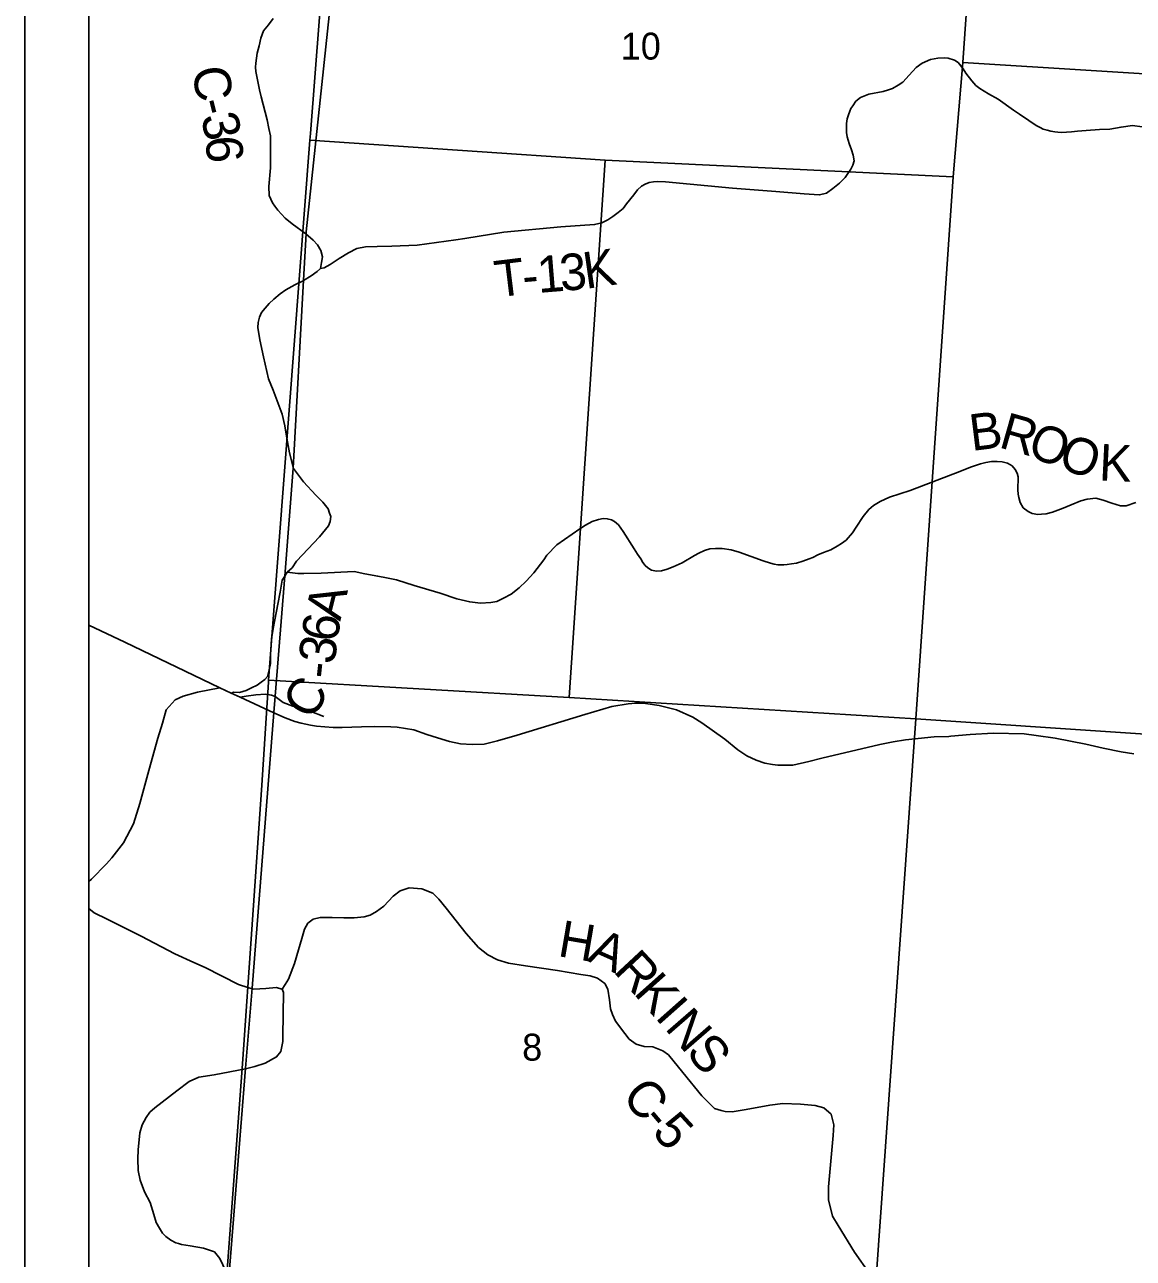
# Model space of a CAD drawing. Extents: x 0 to 34, y 0 to 22.
# Drawn here: x 2 to 3.724, y 16.952 to 18.871 of the extents above; entities that cross this region are included whole.
import ezdxf

# ---------------------------------------------------------------- set-up
doc = ezdxf.new("R2010")
doc.units = 0
for name, color, linetype in [('GM_X_Corporation', 7, 'Continuous'), ('GM_X_County_Road', 7, 'Continuous'), ('GM_X_County_Road_Text', 7, 'Continuous'), ('GM_X_Section_Text', 7, 'Continuous'), ('GM_X_Township_Road', 7, 'Continuous'), ('GM_X_Township_Road_Text', 7, 'Continuous'), ('GM_X_Township_Text', 7, 'Continuous'), ('GM_X_US_Route', 7, 'Continuous'), ('SH_Data', 7, 'Continuous')]:
    doc.layers.add(name, color=color, linetype=linetype)

msp = doc.modelspace()

# ---------------------------------------------------------------- linework, layer by layer
at = {"layer": 'GM_X_Corporation'}
msp.add_lwpolyline([(6.4774, 18.0202), (6.488, 18.1751), (6.5242, 18.7061), (6.5297, 18.7882), (6.5448, 18.981), (6.5455, 18.9878), (6.5461, 19.0017), (6.5463, 19.0089), (6.5469, 19.0218), (6.548, 19.0466), (6.5487, 19.0617), (6.5495, 19.082), (6.5503, 19.0966), (6.5514, 19.1091), (6.5523, 19.1179), (6.5529, 19.1264), (6.5537, 19.1382), (6.5541, 19.1447), (6.5536, 19.1514), (6.5814, 19.5334), (6.6608, 20.6694), (6.6768, 20.9), (2.1, 20.9), (2.1, 14.1)], dxfattribs=at)
for points in [[(3.5308, 19.8461), (4.5379, 19.7849), (4.465, 18.749), (3.459, 18.812), (3.474, 19.0276), (3.5026, 19.4408)], [(2.4767, 19.0934), (3.474, 19.0276), (3.459, 18.812), (3.4438, 18.6342), (2.9025, 18.6602), (2.4436, 18.6909), (2.4444, 18.7015), (2.4582, 18.8825)], [(4.465, 18.749), (4.3947, 17.724), (3.3856, 17.7912), (3.4438, 18.6342), (3.459, 18.812)], [(2.9025, 18.6602), (2.8467, 17.8245), (2.3793, 17.8512), (2.4436, 18.6909)], [(3.4438, 18.6342), (3.3856, 17.7912), (2.8467, 17.8245), (2.9025, 18.6602)], [(2.3791, 17.8483), (2.3793, 17.8512), (2.8467, 17.8245), (3.3856, 17.7912), (3.312, 16.7534), (2.3064, 16.8224), (2.3386, 17.2547), (2.3688, 17.6879)], [(3.3856, 17.7912), (4.3947, 17.724), (4.3249, 16.693), (3.312, 16.7534)]]:
    msp.add_lwpolyline(points, close=True, dxfattribs=at)
at = {"layer": 'GM_X_County_Road'}
for points in [[(2.3864, 18.8801), (2.3791, 18.8703), (2.3714, 18.861), (2.3673, 18.8496), (2.3644, 18.838), (2.3616, 18.8264), (2.3606, 18.8187), (2.3595, 18.8107), (2.359, 18.8045), (2.3593, 18.7981), (2.3603, 18.7926), (2.3624, 18.7823), (2.3652, 18.7692), (2.3678, 18.7586), (2.3771, 18.7225), (2.3799, 18.7094), (2.382, 18.6978), (2.3822, 18.6482), (2.3799, 18.6191), (2.3802, 18.6049), (2.3853, 18.5938), (2.3892, 18.5884)], [(2.3892, 18.5884), (2.3936, 18.5822), (2.4049, 18.5698), (2.416, 18.5608), (2.4374, 18.5456), (2.4488, 18.5358), (2.4552, 18.5286), (2.4604, 18.5196), (2.4632, 18.5098), (2.4617, 18.5007), (2.4602, 18.4915), (2.4549, 18.4869), (2.4456, 18.4803), (2.4338, 18.473), (2.4322, 18.472), (2.4199, 18.4663), (2.406, 18.4585), (2.3971, 18.4521), (2.3874, 18.4441), (2.3804, 18.4373), (2.3738, 18.4301), (2.3683, 18.4229), (2.3651, 18.4159), (2.363, 18.4077), (2.3626, 18.3998), (2.3658, 18.3808), (2.3715, 18.3542), (2.3793, 18.32), (2.3862, 18.3024), (2.4005, 18.2648), (2.4045, 18.247), (2.4079, 18.2277), (2.4119, 18.2051), (2.4179, 18.1808), (2.4335, 18.1597), (2.4528, 18.139), (2.4637, 18.1281), (2.472, 18.118), (2.4742, 18.1111), (2.4759, 18.1057), (2.4748, 18.0983), (2.4723, 18.0913), (2.4587, 18.0744), (2.4227, 18.0363), (2.4159, 18.0263), (2.4084, 18.0193), (2.425, 18.0175), (2.434, 18.0175), (2.4608, 18.0179), (2.5126, 18.0203), (2.5292, 18.0166), (2.5491, 18.0129), (2.5626, 18.0105), (2.578, 18.0072), (2.6058, 17.9988), (2.6461, 17.9865), (2.6721, 17.9779), (2.6922, 17.973), (2.7086, 17.971), (2.7247, 17.972), (2.7342, 17.974), (2.7446, 17.9788), (2.7563, 17.9853), (2.769, 17.9951), (2.78, 18.0052), (2.7915, 18.0181), (2.8072, 18.0383), (2.812, 18.0459), (2.8273, 18.0619), (2.8633, 18.0867), (2.8719, 18.0924), (2.8826, 18.0983), (2.8924, 18.1014), (2.8996, 18.1028), (2.9059, 18.1024), (2.9123, 18.1008), (2.917, 18.0981), (2.9235, 18.0928), (2.9309, 18.0828), (2.9479, 18.0557), (2.953, 18.0471), (2.9579, 18.04), (2.9612, 18.0346), (2.9651, 18.0295), (2.9688, 18.026), (2.9749, 18.0224), (2.9825, 18.0209), (2.9901, 18.0213), (2.9989, 18.024), (3.0085, 18.0279), (3.0222, 18.0338), (3.0417, 18.0455), (3.0484, 18.0488), (3.0572, 18.0533), (3.0656, 18.0555), (3.074, 18.0563), (3.0847, 18.0561), (3.0986, 18.0543), (3.1111, 18.0502), (3.1481, 18.0369), (3.1598, 18.0336), (3.1653, 18.0318), (3.1709, 18.031), (3.1762, 18.0308), (3.1807, 18.0306), (3.1858, 18.0314), (3.1924, 18.0324), (3.2001, 18.0336), (3.2102, 18.0363), (3.2198, 18.04), (3.2257, 18.0424), (3.2333, 18.0461), (3.2421, 18.0498), (3.2538, 18.0543), (3.2636, 18.0598), (3.2704, 18.0639), (3.2772, 18.0692), (3.2874, 18.0807), (3.2929, 18.0891), (3.3036, 18.1058), (3.3125, 18.1167), (3.3197, 18.1229), (3.3304, 18.1292), (3.3449, 18.1358), (3.377, 18.1466), (3.4542, 18.1761), (3.471, 18.1827), (3.4862, 18.1878), (3.4946, 18.19), (3.5034, 18.1913), (3.512, 18.1913), (3.5199, 18.1909), (3.5285, 18.189), (3.5355, 18.1845), (3.5404, 18.1792), (3.5433, 18.1733), (3.5447, 18.1677), (3.5447, 18.1606), (3.5443, 18.154), (3.5443, 18.1473), (3.5449, 18.1409), (3.546, 18.1354), (3.548, 18.1276), (3.5525, 18.1196), (3.5604, 18.1139), (3.5668, 18.1105), (3.5757, 18.1092), (3.5809, 18.1094), (3.5886, 18.1102), (3.5981, 18.1127), (3.6146, 18.1188), (3.6275, 18.1241), (3.6423, 18.1301), (3.6521, 18.1329), (3.6656, 18.1346), (3.6771, 18.1315), (3.6906, 18.1268), (3.7039, 18.1227), (3.7127, 18.1223), (3.7277, 18.1276)], [(2.3825, 17.8794), (2.3824, 17.891), (2.384, 17.9158), (2.3862, 17.9315), (2.3939, 17.9694), (2.3971, 17.988), (2.4005, 18.0067), (2.4046, 18.0132), (2.4084, 18.0193)], [(2.3211, 17.8312), (2.3251, 17.8327), (2.334, 17.8324), (2.3446, 17.8351), (2.3528, 17.8396), (2.3615, 17.8436), (2.3675, 17.8481), (2.3732, 17.8527), (2.3774, 17.8572), (2.38, 17.8673), (2.3825, 17.8775), (2.3825, 17.8794)], [(2.1, 17.5386), (2.1039, 17.5421), (2.127, 17.5659), (2.1355, 17.5754), (2.1536, 17.5985), (2.1691, 17.6279), (2.1789, 17.6596), (2.1932, 17.7112), (2.2071, 17.7612), (2.2141, 17.7843), (2.2198, 17.8051), (2.2339, 17.821), (2.2467, 17.8264), (2.2688, 17.833), (2.3036, 17.8397)], [(2.4004, 17.3707), (2.405, 17.3782), (2.4105, 17.3867), (2.4195, 17.411), (2.4258, 17.4323), (2.4311, 17.4498), (2.4352, 17.4641), (2.4403, 17.4735), (2.4485, 17.48), (2.4597, 17.4823), (2.4783, 17.4825), (2.4962, 17.4821), (2.5126, 17.4817), (2.5277, 17.4835), (2.5374, 17.4859), (2.5472, 17.4916), (2.5583, 17.5002), (2.5729, 17.5154), (2.584, 17.5237), (2.5981, 17.5286), (2.6175, 17.527), (2.6346, 17.5202), (2.6442, 17.511), (2.6552, 17.497), (2.6865, 17.4574), (2.7057, 17.4357), (2.7204, 17.4245), (2.7355, 17.4163), (2.7526, 17.4116), (2.7787, 17.4073), (2.8283, 17.4), (2.8649, 17.3939), (2.8792, 17.3916), (2.8908, 17.3882), (2.902, 17.3798), (2.9067, 17.3708), (2.9094, 17.3545), (2.9112, 17.3406), (2.9141, 17.3316), (2.9188, 17.321), (2.9335, 17.3018), (2.9398, 17.2934), (2.9508, 17.2855), (2.9633, 17.282), (2.9768, 17.281), (2.9921, 17.2749), (3.001, 17.2687), (3.0233, 17.2412), (3.0531, 17.2053), (3.0727, 17.1855), (3.0829, 17.182), (3.0894, 17.1808), (3.1003, 17.1804), (3.1217, 17.184), (3.1588, 17.1904), (3.1788, 17.1932), (3.2064, 17.1922), (3.2291, 17.1899), (3.2429, 17.1865), (3.254, 17.1765), (3.2581, 17.1601), (3.2572, 17.1432), (3.2498, 17.0638), (3.2501, 17.0436), (3.2561, 17.0177), (3.2648, 17.0032), (3.2903, 16.9619), (3.3138, 16.9287)], [(2.2633, 17.4123), (2.2337, 17.4259), (2.1812, 17.4531), (2.1284, 17.4798), (2.1082, 17.4894), (2.1, 17.4966)], [(2.4015, 17.2977), (2.4024, 17.3659), (2.4004, 17.3707), (2.3913, 17.3737), (2.3748, 17.3722), (2.3564, 17.371), (2.3537, 17.3717), (2.3472, 17.3735), (2.3327, 17.3784), (2.2805, 17.4045), (2.2633, 17.4123)], [(2.2391, 16.9754), (2.2352, 16.9765), (2.2271, 16.9804), (2.2195, 16.9861), (2.2143, 16.9914), (2.2096, 16.9992), (2.2046, 17.0081), (2.201, 17.0203), (2.1951, 17.0394), (2.1864, 17.0556), (2.1795, 17.074), (2.1764, 17.0892), (2.1758, 17.107), (2.1763, 17.1213), (2.1789, 17.1474), (2.1829, 17.1601), (2.1889, 17.1715), (2.1947, 17.1799), (2.2026, 17.1862), (2.2367, 17.2127), (2.2559, 17.2273), (2.2707, 17.234), (2.2947, 17.2379), (2.3433, 17.2473), (2.358, 17.2508), (2.3739, 17.2558), (2.3918, 17.2657), (2.3983, 17.2741), (2.4014, 17.2893), (2.4015, 17.2977)], [(2.3184, 16.8369), (2.3277, 16.8395), (2.338, 16.8445), (2.343, 16.8506), (2.344, 16.8563), (2.3435, 16.8683), (2.3341, 16.8856), (2.3179, 16.9213), (2.3037, 16.9519), (2.295, 16.9625), (2.2781, 16.9682), (2.2575, 16.9717), (2.244, 16.974), (2.2391, 16.9754)]]:
    msp.add_lwpolyline(points, dxfattribs=at)
at = {"layer": 'GM_X_Township_Road'}
for points in [[(2.4602, 18.4915), (2.4657, 18.4926), (2.4752, 18.4977), (2.489, 18.5072), (2.5034, 18.5159), (2.5165, 18.5224), (2.5299, 18.525), (2.5479, 18.5258), (2.5707, 18.5262), (2.6103, 18.5279), (2.6704, 18.5362), (2.6845, 18.5384), (2.745, 18.5478), (2.8339, 18.5565), (2.8862, 18.5599), (2.8974, 18.5625), (2.9067, 18.5671), (2.9148, 18.5722), (2.923, 18.5785), (2.9305, 18.5851), (2.9357, 18.5923), (2.9471, 18.6062), (2.9531, 18.6139), (2.959, 18.6196), (2.965, 18.6228), (2.9711, 18.6255), (2.9779, 18.6262), (2.9847, 18.6266), (2.9965, 18.6264), (3.1007, 18.6166), (3.1682, 18.6114), (3.2123, 18.6075), (3.2279, 18.6067), (3.2362, 18.6061), (3.247, 18.6086), (3.2567, 18.6157), (3.2671, 18.6243), (3.2758, 18.6332), (3.2802, 18.6395), (3.2847, 18.6459), (3.2876, 18.6522), (3.2898, 18.6592), (3.2885, 18.6677), (3.2857, 18.6759), (3.2823, 18.6857), (3.2792, 18.6963), (3.2781, 18.7032), (3.2777, 18.7109), (3.2779, 18.7168), (3.2792, 18.7242), (3.2811, 18.7303), (3.2832, 18.7361), (3.2849, 18.7401), (3.2876, 18.7443), (3.2923, 18.7517), (3.2999, 18.7572), (3.3073, 18.7604), (3.3128, 18.7625), (3.3349, 18.767), (3.3433, 18.7693), (3.3495, 18.7714), (3.3582, 18.7767), (3.3656, 18.7812), (3.3755, 18.7922), (3.3861, 18.8042), (3.3956, 18.8106), (3.4088, 18.8163), (3.4202, 18.8186), (3.4304, 18.8191), (3.4361, 18.8186), (3.4458, 18.8155), (3.4515, 18.8119), (3.4591, 18.8021), (3.4636, 18.7951), (3.4729, 18.7833), (3.4793, 18.7759), (3.4854, 18.7712), (3.4985, 18.7632), (3.514, 18.7549), (3.5377, 18.738), (3.5472, 18.7316), (3.5616, 18.7217), (3.5728, 18.7138), (3.579, 18.7107), (3.5836, 18.7081), (3.59, 18.7064), (3.5959, 18.7049), (3.6018, 18.7041), (3.6065, 18.7035), (3.6129, 18.7032), (3.6201, 18.7035), (3.6279, 18.7041), (3.6372, 18.7052), (3.6508, 18.706), (3.6715, 18.7077), (3.6874, 18.7083), (3.705, 18.7115), (3.7225, 18.714), (3.7376, 18.7119)], [(2.3351, 17.8251), (2.3442, 17.8264), (2.3595, 17.8287), (2.3745, 17.8294), (2.3836, 17.828), (2.3897, 17.826)], [(2.3897, 17.826), (2.4022, 17.8169), (2.417, 17.811), (2.4331, 17.807), (2.4437, 17.8034), (2.4651, 17.7951)]]:
    msp.add_lwpolyline(points, dxfattribs=at)
at = {"layer": 'GM_X_Township_Text'}
msp.add_lwpolyline([(2.227, 15.7788), (2.2908, 16.5824), (2.3045, 16.7554), (2.3047, 16.7573), (2.3109, 16.8355), (2.3177, 16.9219), (2.3436, 17.248), (2.3535, 17.3723), (2.3875, 17.8009), (2.3895, 17.8265), (2.4044, 18.0137), (2.4049, 18.0199), (2.4177, 18.1813), (2.4336, 18.4735), (2.4376, 18.5458), (2.4377, 18.5488), (2.4735, 18.8849), (2.5013, 19.2713), (2.5435, 19.8534), (2.5683, 20.2001), (2.5873, 20.4639), (2.6187, 20.9)], dxfattribs=at)
at = {"layer": 'GM_X_US_Route'}
for points in [[(2.1, 17.9368), (2.1558, 17.9103), (2.3036, 17.8397), (2.3211, 17.8312), (2.3351, 17.8251)], [(2.3351, 17.8251), (2.3873, 17.8005), (2.405, 17.7928), (2.4199, 17.7873), (2.4301, 17.7845), (2.4444, 17.7817), (2.4537, 17.78), (2.4796, 17.7776), (2.4939, 17.7778), (2.5237, 17.7789), (2.5436, 17.7793), (2.5693, 17.7789), (2.5791, 17.7783), (2.592, 17.7763), (2.6052, 17.7742), (2.6251, 17.767), (2.6418, 17.7618), (2.6606, 17.7558), (2.6775, 17.7525), (2.6956, 17.7515), (2.7146, 17.7521), (2.7352, 17.7571), (2.7659, 17.7657), (2.871, 17.7982), (2.9131, 17.8107), (2.9382, 17.8146), (2.9497, 17.8155), (2.9587, 17.8155), (2.9655, 17.8152), (2.9864, 17.8118), (3.0135, 17.8051), (3.0392, 17.7938), (3.0532, 17.785), (3.0887, 17.7595), (3.1092, 17.7432), (3.1231, 17.7337), (3.1376, 17.7268), (3.1508, 17.7223), (3.1631, 17.7203), (3.1709, 17.7192), (3.1843, 17.719), (3.1944, 17.7195), (3.2193, 17.7251), (3.2394, 17.73), (3.33, 17.7512), (3.3505, 17.7556), (3.3696, 17.7584), (3.4145, 17.7631), (3.4372, 17.7638), (3.4402, 17.7641)], [(3.4402, 17.7641), (3.4703, 17.767), (3.506, 17.769), (3.554, 17.7679), (3.5728, 17.7653), (3.6022, 17.7614), (3.65, 17.7521), (3.6772, 17.7456), (3.7049, 17.74), (3.7246, 17.7368)]]:
    msp.add_lwpolyline(points, dxfattribs=at)
at = {"layer": 'SH_Data'}
for p, q in [((2, 21), (2, 14)), ((2.1, 20.9), (2.1, 14.1))]:
    msp.add_line(p, q, dxfattribs=at)

# ---------------------------------------------------------------- texts
at = {"layer": 'GM_X_County_Road_Text'}
for s, rotation, p in [('C', 278.2399, (2.2604, 18.8025)), ('-', 283.8873, (2.2683, 18.7504)), ('3', 282.3346, (2.2738, 18.7281)), ('6', 274.2606, (2.281, 18.696)), ('B', 7.0863, (3.4726, 18.2077)), ('R', 344.1913, (3.513, 18.2139)), ('O', 338.5605, (3.5565, 18.2017)), ('O', 340.1137, (3.6046, 18.1828)), ('K', 357.2828, (3.6698, 18.1622)), ('A', 76.0866, (2.4907, 17.9421)), ('6', 82.2299, (2.4863, 17.9093)), ('3', 82.1199, (2.4815, 17.8747)), ('-', 83.7695, (2.479, 17.8522)), ('C', 58.9748, (2.4466, 17.7872)), ('H', 350.3005, (2.8275, 17.4226)), ('A', 336.1174, (2.8732, 17.4153)), ('R', 312.9269, (2.914, 17.3985)), ('K', 311.6057, (2.9456, 17.3646)), ('I', 311.5259, (2.9788, 17.3272)), ('N', 310.9656, (2.9941, 17.3099)), ('S', 309.7685, (3.0267, 17.2724)), ('C', 309.5022, (2.9269, 17.2037)), ('-', 310.2392, (2.9571, 17.167)), ('5', 312.5997, (2.9739, 17.1473))]:
    msp.add_text(s, height=0.0568, rotation=rotation, dxfattribs=at).set_placement(p)
at = {"layer": 'GM_X_Section_Text'}
for s, height, p in [('10', 0.04186, (2.9269, 18.8164)), ('8', 0.0419, (2.7736, 17.2598))]:
    msp.add_text(s, height=height, rotation=0, dxfattribs=at).set_placement(p)
at = {"layer": 'GM_X_Township_Road_Text'}
for s, rotation, p in [('1', 4.6625, (2.799, 18.4535)), ('3', 4.7312, (2.8339, 18.4564)), ('K', 8.2473, (2.8726, 18.4597)), ('T', 6.9602, (2.7341, 18.4464)), ('-', 4.9322, (2.7758, 18.4515))]:
    msp.add_text(s, height=0.0568, rotation=rotation, dxfattribs=at).set_placement(p)

doc.saveas('drawing.dxf')
